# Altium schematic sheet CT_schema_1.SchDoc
size 549 x 521 mm
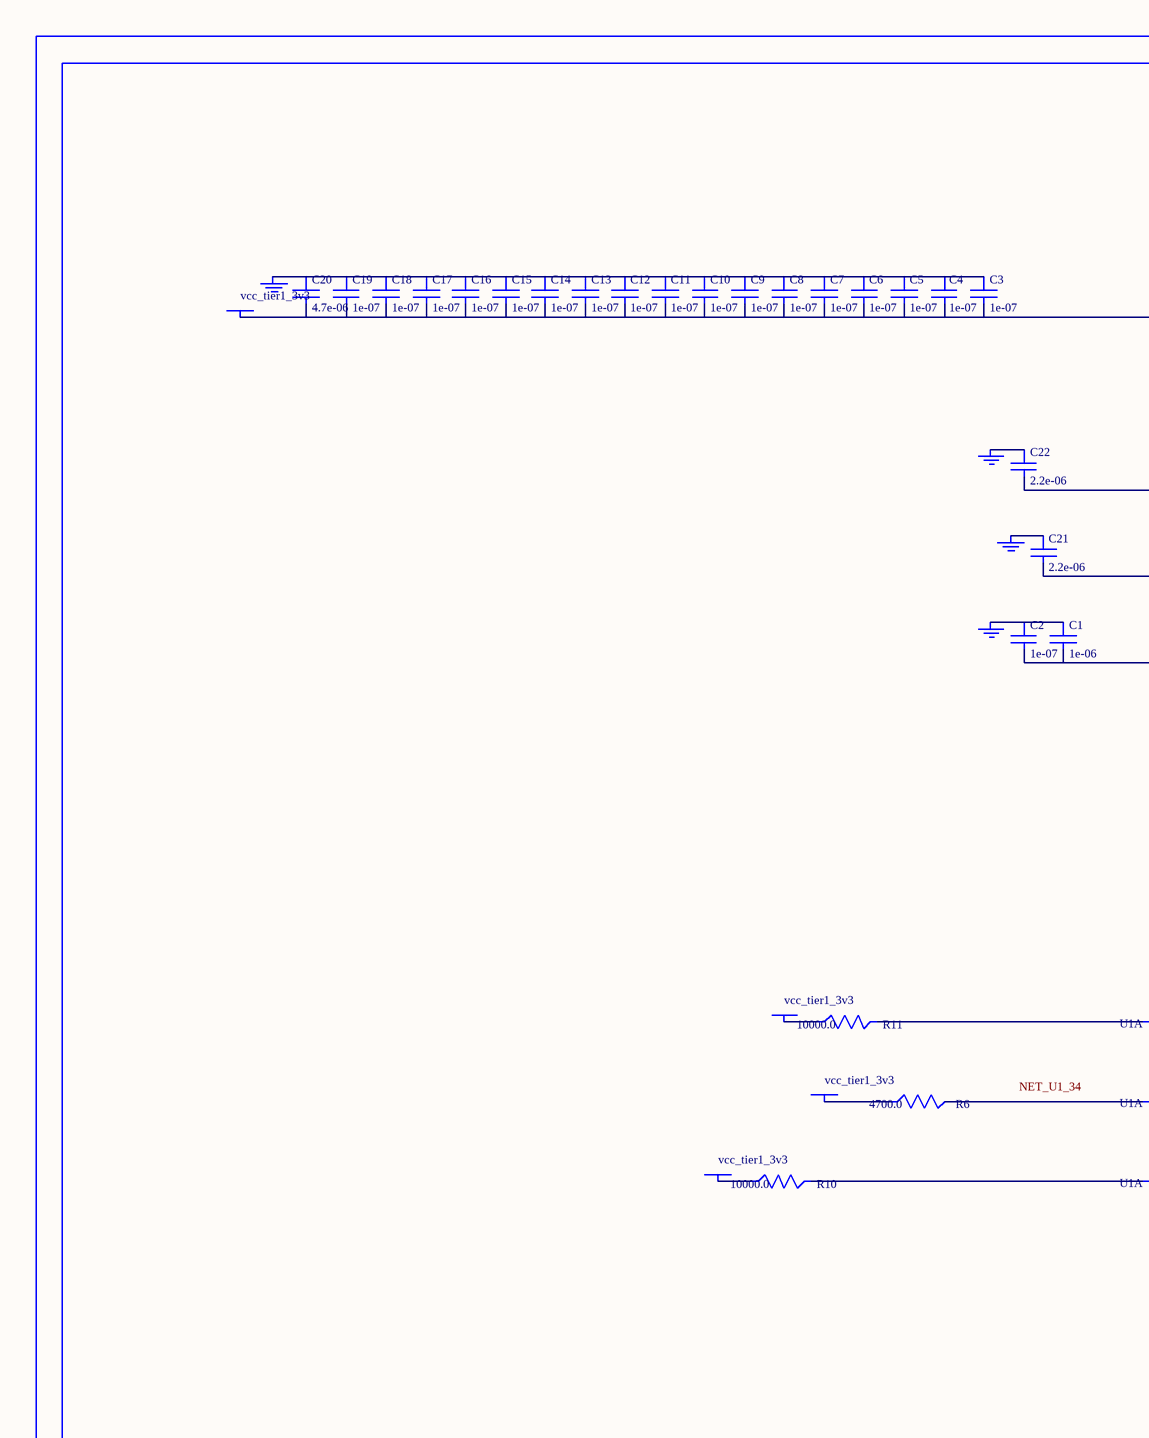
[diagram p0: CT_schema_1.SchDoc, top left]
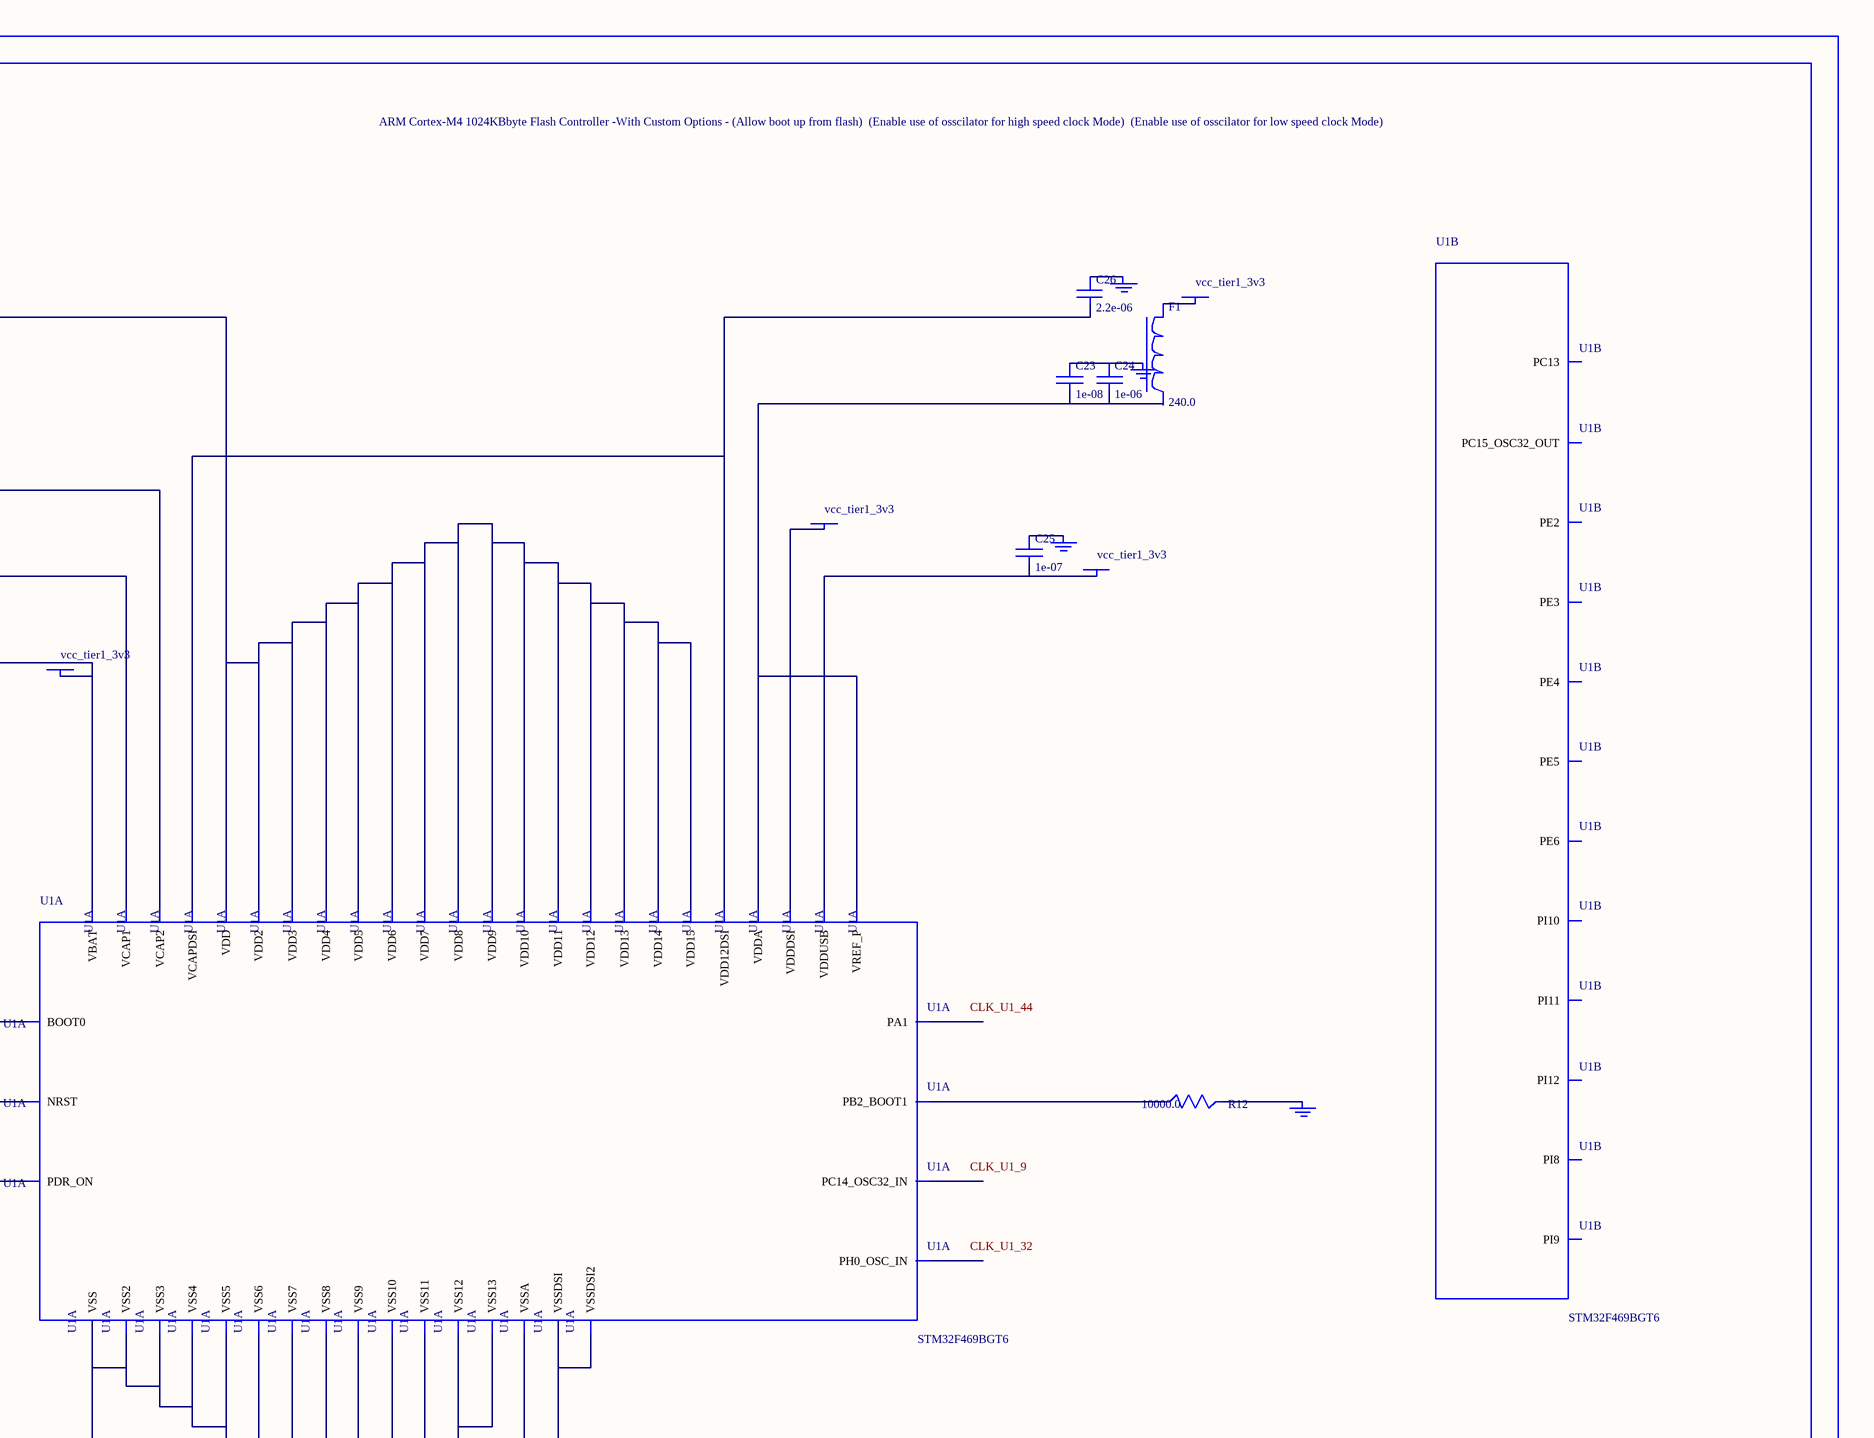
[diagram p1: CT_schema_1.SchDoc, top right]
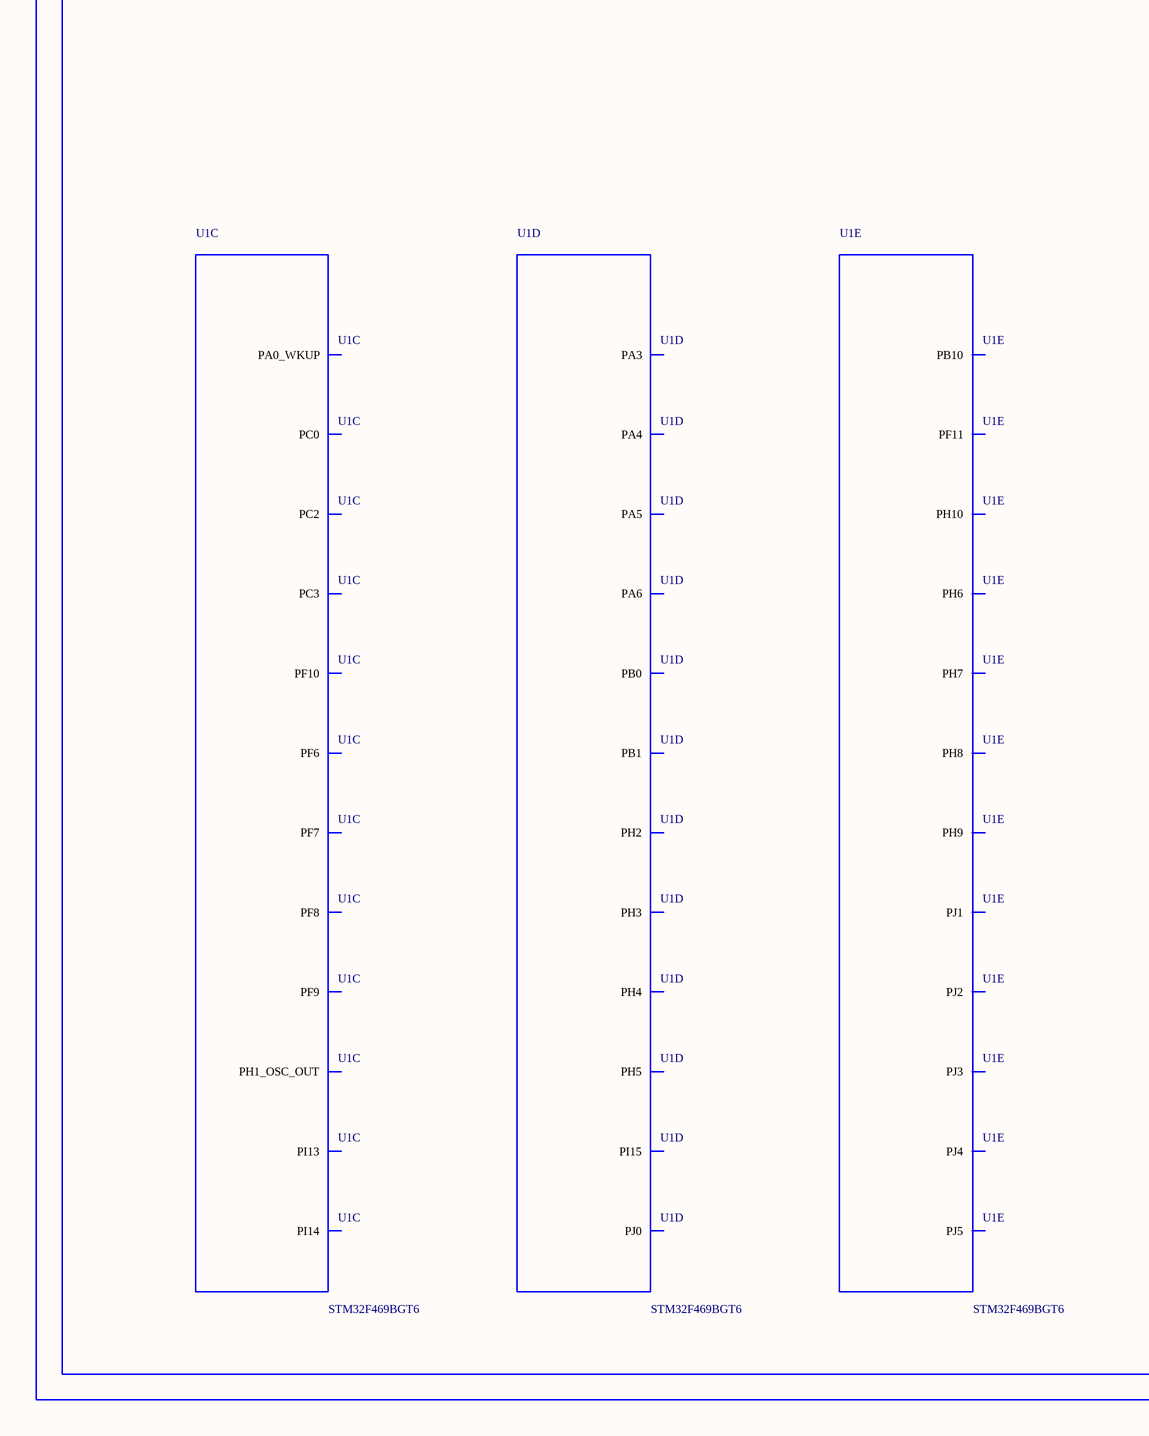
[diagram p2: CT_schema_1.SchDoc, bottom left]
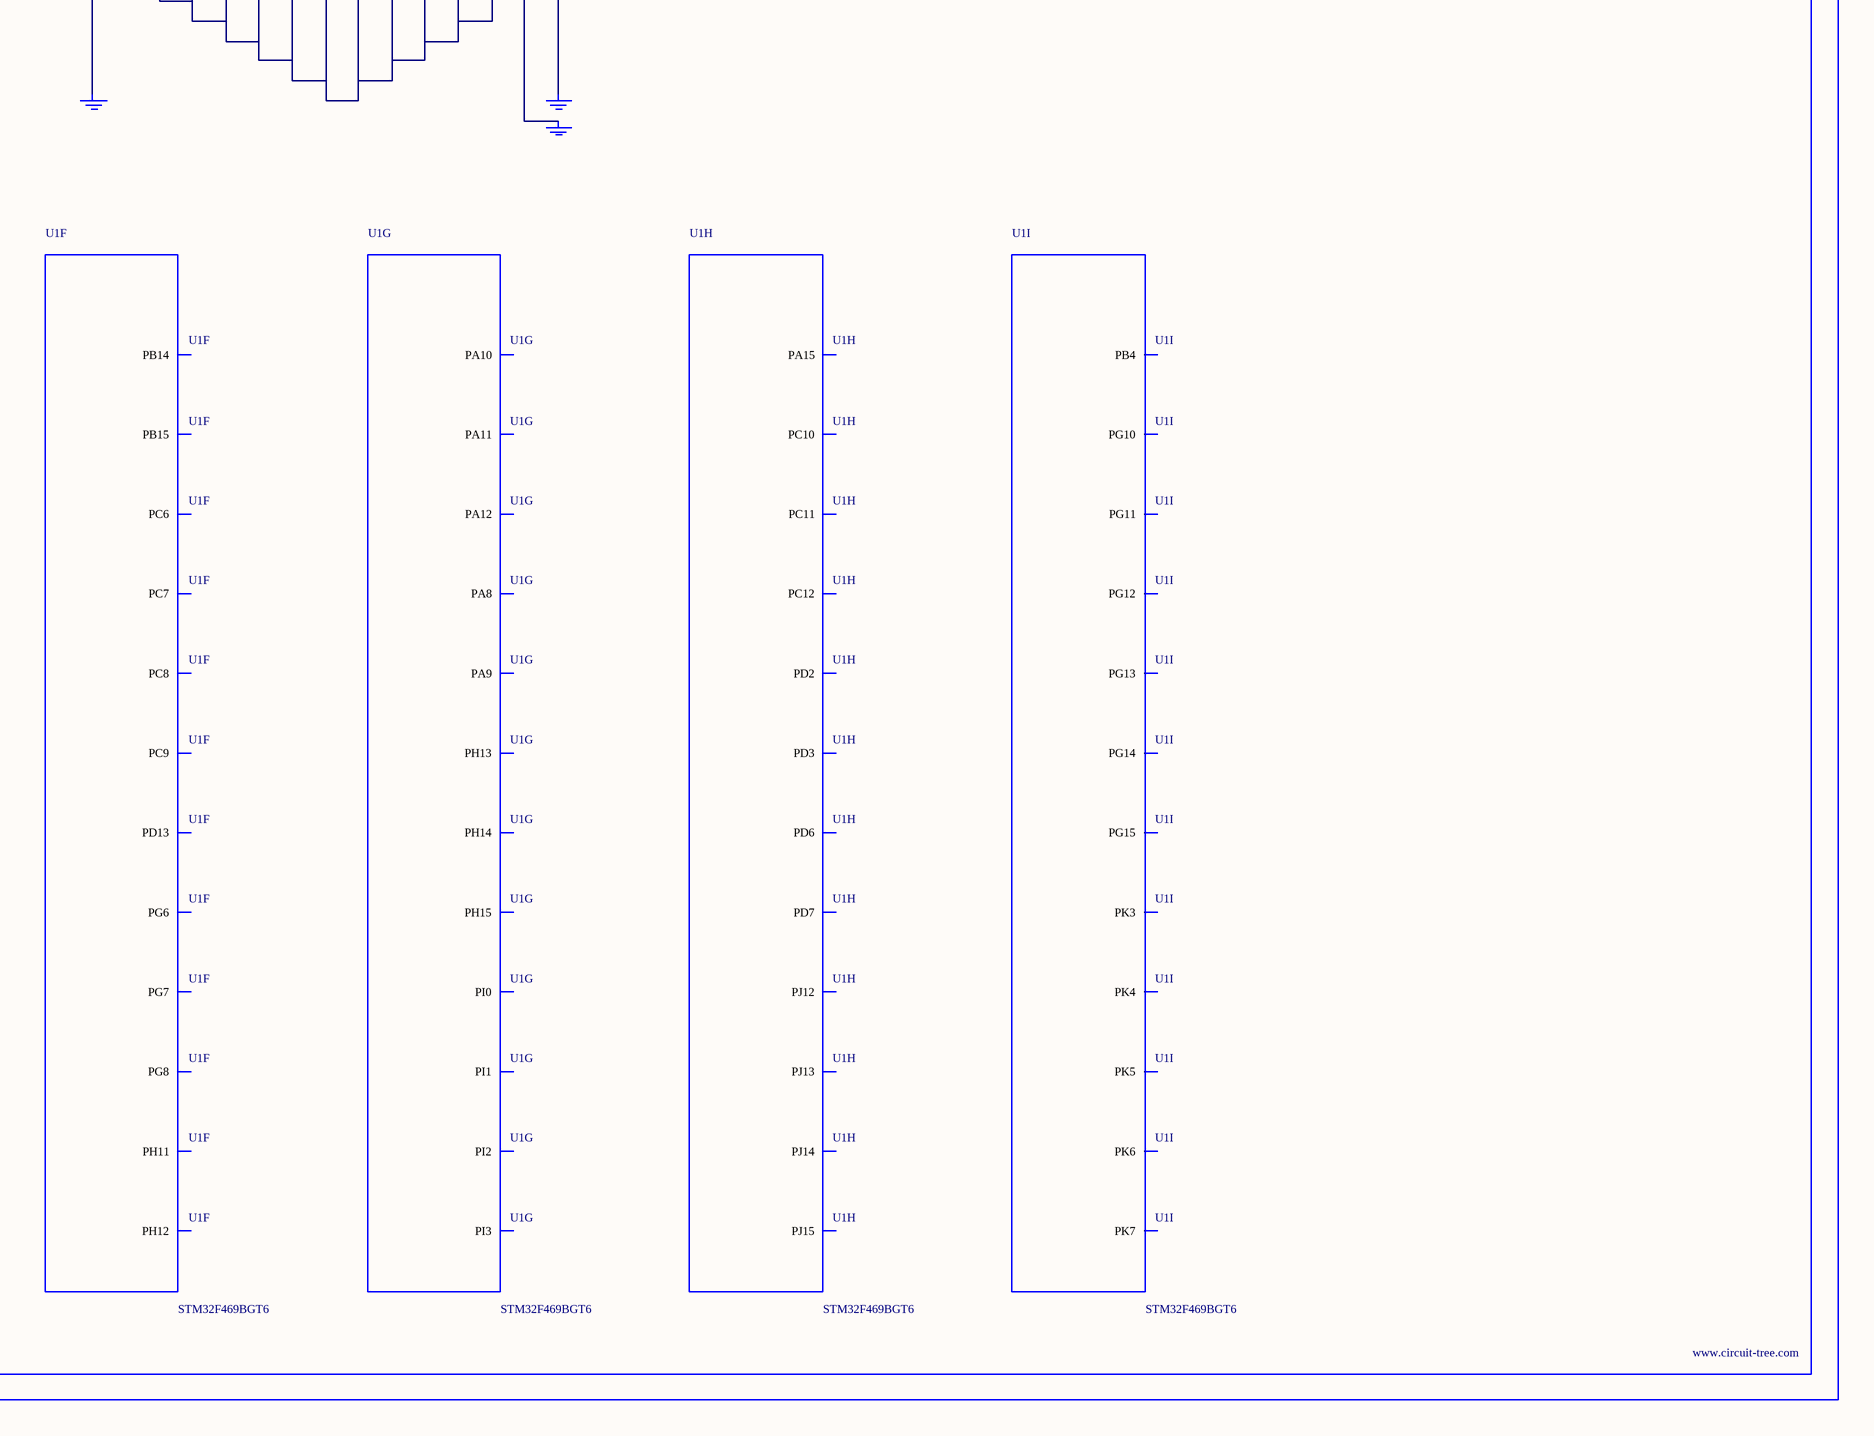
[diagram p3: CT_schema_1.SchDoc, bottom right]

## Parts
BORDER0  (no value)
C1  1e-06  [C0603]
C2  1e-07  [C0603]
C3  1e-07  [C0603]
C4  1e-07  [C0603]
C5  1e-07  [C0603]
C6  1e-07  [C0603]
C7  1e-07  [C0603]
C8  1e-07  [C0603]
C9  1e-07  [C0603]
C10  1e-07  [C0603]
C11  1e-07  [C0603]
C12  1e-07  [C0603]
C13  1e-07  [C0603]
C14  1e-07  [C0603]
C15  1e-07  [C0603]
C16  1e-07  [C0603]
C17  1e-07  [C0603]
C18  1e-07  [C0603]
C19  1e-07  [C0603]
C20  4.7e-06  [C0603]
C21  2.2e-06  [C0603]
C22  2.2e-06  [C0603]
C23  1e-08  [C0603]
C24  1e-06  [C0603]
C25  1e-07  [C0603]
C26  2.2e-06  [C0603]
F1  240.0  [L0603]
GND_INSTANCE_0_0  (no value)
GND_INSTANCE_0_1  (no value)
GND_INSTANCE_0_2  (no value)
GND_INSTANCE_0_3  (no value)
GND_INSTANCE_0_4  (no value)
GND_INSTANCE_0_5  (no value)
GND_INSTANCE_0_6  (no value)
GND_INSTANCE_0_7  (no value)
GND_INSTANCE_0_8  (no value)
GND_INSTANCE_0_9  (no value)
GND_INSTANCE_0_10  (no value)
POWER_INSTANCE_0_0  vcc_tier1_3v3
POWER_INSTANCE_0_1  vcc_tier1_3v3
POWER_INSTANCE_0_2  vcc_tier1_3v3
POWER_INSTANCE_0_3  vcc_tier1_3v3
POWER_INSTANCE_0_4  vcc_tier1_3v3
POWER_INSTANCE_0_5  vcc_tier1_3v3
POWER_INSTANCE_0_6  vcc_tier1_3v3
POWER_INSTANCE_0_7  vcc_tier1_3v3
R6  4700.0  [R0603]
R10  10000.0  [R0603]
R11  10000.0  [R0603]
R12  10000.0  [R0603]
U1  STM32F469BGT6  [LQFP208]  (parts A,B,C,D,E,F,G,H,I of 16)

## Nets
NetC1_1: C1.1 C2.1 GND_INSTANCE_0_0.0(GND)
NetC1_2: C1.2 C2.2 POWER_INSTANCE_0_0.0(PWR) U1.6(VBAT)
NetC3_1: C3.1 C4.1 C5.1 C6.1 C7.1 C8.1 C9.1 C10.1 C11.1 C12.1 C13.1 C14.1 C15.1 C16.1 C17.1 C18.1 C19.1 C20.1 GND_INSTANCE_0_1.0(GND)
NetC3_2: C3.2 C4.2 C5.2 C6.2 C7.2 C8.2 C9.2 C10.2 C11.2 C12.2 C13.2 C14.2 C15.2 C16.2 C17.2 C18.2 C19.2 C20.2 POWER_INSTANCE_0_1.0(PWR) U1.15(VDD) U1.26(VDD2) U1.39(VDD3) U1.52(VDD4) U1.59(VDD5) U1.73(VDD6) U1.83(VDD7) U1.94(VDD8) U1.103(VDD9) U1.115(VDD10) U1.150(VDD11) U1.158(VDD12) U1.171(VDD13) U1.185(VDD14) U1.204(VDD15)
NetC21_1: C21.1 GND_INSTANCE_0_5.0(GND)
NetC21_2: C21.2 U1.92(VCAP1)
NetC22_1: C22.1 GND_INSTANCE_0_8.0(GND)
NetC22_2: C22.2 U1.148(VCAP2)
NetC23_1: C23.1 C24.1 GND_INSTANCE_0_3.0(GND)
NetC23_2: C23.2 C24.2 U1.41(VREF_P) U1.42(VDDA)
NetC25_1: C25.1 GND_INSTANCE_0_7.0(GND)
NetC25_2: C25.2 POWER_INSTANCE_0_4.0(PWR) U1.137(VDDUSB)
NetC26_1: C26.1 GND_INSTANCE_0_6.0(GND)
NetC26_2: C26.2 U1.119(VCAPDSI) U1.125(VDD12DSI)
NetF1_1: F1.1 POWER_INSTANCE_0_2.0(PWR)
NetGND_INSTANCE_0_2_0: GND_INSTANCE_0_2.0(GND) U1.40(VSSA)
NetGND_INSTANCE_0_4_0: GND_INSTANCE_0_4.0(GND) R12.2
NetGND_INSTANCE_0_9_0: GND_INSTANCE_0_9.0(GND) U1.14(VSS) U1.25(VSS2) U1.51(VSS3) U1.60(VSS4) U1.72(VSS5) U1.82(VSS6) U1.93(VSS7) U1.114(VSS8) U1.136(VSS9) U1.149(VSS10) U1.170(VSS11) U1.184(VSS12) U1.202(VSS13)
NetGND_INSTANCE_0_10_0: GND_INSTANCE_0_10.0(GND) U1.122(VSSDSI) U1.128(VSSDSI2)
NetPOWER_INSTANCE_0_3_0: POWER_INSTANCE_0_3.0(PWR) U1.118(VDDDSI)
NetPOWER_INSTANCE_0_5_0: POWER_INSTANCE_0_5.0(PWR) R11.1
NetPOWER_INSTANCE_0_6_0: POWER_INSTANCE_0_6.0(PWR) R10.1
NetPOWER_INSTANCE_0_7_0: POWER_INSTANCE_0_7.0(PWR) R6.1
NetR6_2: R6.2 U1.34(NRST)
NetR10_2: R10.2 U1.203(PDR_ON)
NetR11_2: R11.2 U1.197(BOOT0)
NetR12_1: R12.1 U1.63(PB2_BOOT1)

Not connected (* = marked no-connect by the designer): F1 2; U1 1(PE2) 2(PE3) 3(PE4) 4(PE5) 5(PE6) 7(PI8) 8(PC13) 9(PC14_OSC32_IN) 10(PC15_OSC32_OUT) 11(PI9) 12(PI10) 13(PI11) 19(PI12) 20(PI13) 21(PI14) 27(PF6) 28(PF7) 29(PF8) 30(PF9) 31(PF10) 32(PH0_OSC_IN) 33(PH1_OSC_OUT) 35(PC0) 37(PC2) 38(PC3) 43(PA0_WKUP) 44(PA1) 46(PH2) 47(PH3) 48(PH4) 49(PH5) 50(PA3) 53(PA4) 54(PA5) 55(PA6) 61(PB0) 62(PB1) 64(PI15) 65(PJ0) 66(PJ1) 67(PJ2) 68(PJ3) 69(PJ4) 70(PF11) 90(PB10) 95(PJ5) 96(PH6) 97(PH7) 98(PH8) 99(PH9) 100(PH10) 101(PH11) 102(PH12) 106(PB14) 107(PB15) 113(PD13) 133(PG6) 134(PG7) 135(PG8) 138(PC6) 139(PC7) 140(PC8) 141(PC9) 142(PA8) 143(PA9) 144(PA10) 145(PA11) 146(PA12) 151(PH13) 152(PH14) 153(PH15) 154(PI0) 155(PI1) 156(PI2) 157(PI3) 160(PA15) 161(PC10) 162(PC11) 163(PC12) 166(PD2) 167(PD3) 172(PD6) 173(PD7) 174(PJ12) 175(PJ13) 176(PJ14) 177(PJ15) 179(PG10) 180(PG11) 181(PG12) 182(PG13) 183(PG14) 186(PK3) 187(PK4) 188(PK5) 189(PK6) 190(PK7) 191(PG15) 193(PB4)

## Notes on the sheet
- Labels drawn without touching a wire or pin: CLK_U1_9, CLK_U1_32, CLK_U1_44, NET_U1_34

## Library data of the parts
BORDER0 = BORDER_PAGE0
C1 C24 = C0603C105K3RACTU
C2-C19 C25 = 06035C104K4Z2A
C20 = GRM188R6YA475KE15D
C21 C22 C26 = C0603C225K8RACTU
C23 = 06035C103K4Z2A
F1 = Z0603C241ASMST
GND_INSTANCE_0_0-GND_INSTANCE_0_10 = GND
POWER_INSTANCE_0_0-POWER_INSTANCE_0_7 = PWR
R6 = RC0603JR-074K7L
R10-R12 = RC0603JR-0710KL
